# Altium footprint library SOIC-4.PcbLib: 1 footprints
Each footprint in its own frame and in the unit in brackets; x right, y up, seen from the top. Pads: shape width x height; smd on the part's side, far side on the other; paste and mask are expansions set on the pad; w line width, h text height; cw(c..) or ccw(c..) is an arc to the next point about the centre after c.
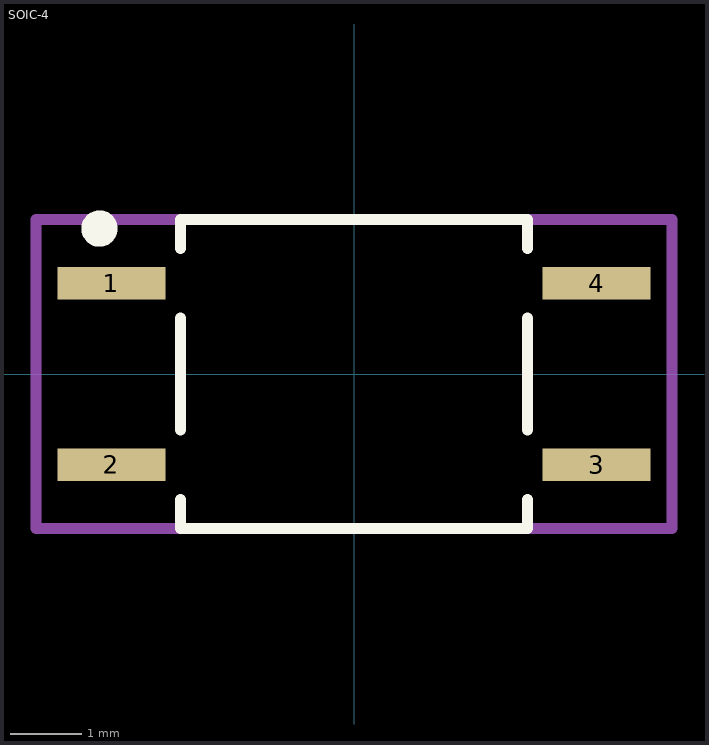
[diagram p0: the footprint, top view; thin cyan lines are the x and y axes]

## SOIC-4 [mil]
pads (4):
  rect 59.37x17.97 smd: 1(-133.47,50) 2(-133.47,-50) 3(133.47,-50) 4(133.47,50)
Top Overlay:
  circle w10: c-140,80 r5
  lines w6: -95.5,-69.13 -95.5,-85 95.5,-85 95.5,-69.13 ; -95.5,-30.87 -95.5,30.87 ; -95.5,69.13 -95.5,85 95.5,85 95.5,69.13 ; 95.5,-30.87 95.5,30.87
Mechanical 15:
  lines w6: -175,-85 -110.5,-85 110.5,-85 175,-85 175,85 110.5,85 -110.5,85 -175,85 -175,-85
3D body "SOP4PIN_PAN.step": height 91.1, standoff 0, extent -141.5,-88.5 141.5,88.5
